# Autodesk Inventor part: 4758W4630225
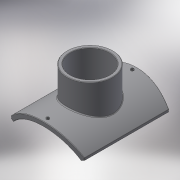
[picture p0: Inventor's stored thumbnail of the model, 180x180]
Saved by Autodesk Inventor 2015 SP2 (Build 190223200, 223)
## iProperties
Created: 2017-10
Part Number: 4758W4630225
Material: Generic
Description: PLASSON LIGHTFIT SADDLE 450-630X225 SPIGOT INLET
Document SubType Name: Modeling
Designer: KIM
Density: 1 g/cm^3
Appearance: Default
Author: KIM
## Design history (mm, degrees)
derived "4758W.ipt"
feature "Solid1::4758W.ipt"
tag "TaggingFeature1"
body "Solid1"
other parameters: "d1" = 22, "d2" = 389, "d4" = 0, "d12" = 340.6, "d13" = 14, "d14" = 189, "d16" = 5 deg, "d18" = 4, "d19" = 14, "d20" = 0, "d21" = 3, "d22" = 0, "d23" = 467, "d24" = 225, "d26" = 191.25, "d28" = 0, "d34" = 6.3, "d39" = 3.15, "d44" = 18.9, "d52" = 0, "d53" = 189, "d55" = 0, "d56" = 3.15, "d_1" = 225, "B_" = 389, "x_" = 22, "D_" = 16
